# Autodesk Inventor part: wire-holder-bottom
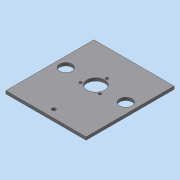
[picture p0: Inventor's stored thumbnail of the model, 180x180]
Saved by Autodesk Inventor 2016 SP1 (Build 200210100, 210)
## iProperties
Created: 2016-06
Part Number: wire-holder-bottom
Material: Generic
Document SubType Name: Modeling
Designer: Mohamed A.
Density: 1 g/cm^3
Appearance: Default
Author: Mohamed A.
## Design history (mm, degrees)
sketch "Sketch1"
  geometry: L1 (-41, 35)-(41, 35); L2 (41, 35)-(41, -35); L3 (41, -35)-(-41, -35); L4 (-41, -35)-(-41, 35); L5 (-41, 35)-(41, -35); L6 (41, 35)-(-41, -35); 1 further point
  constraints: 12 end point, 2 midpoint, 2 parallel, 1 horizontal, 1 perpendicular
  dimensions: "d0" = 82 distance of L2.end L3.end; "d1" = 70 distance of L1.end L2.end
extrude "Extrusion1" new body sketch "Sketch1" distance "d2" = 3; taper "d3" = 0 deg
sketch "Sketch2"
  geometry: C1 r 8.05 at (0, -4) reference; C2 r 2 at (9.922, -9.728) reference; C3 r 2 at (-9.922, -9.728) reference; C4 r 2 at (0, 7.457) reference; C5 r 1.4 at (-9.922, -9.728); C6 r 1.4 at (9.922, -9.728); C7 r 1.4 at (0, 7.457); C8 r 4.7 at (30.7, -4) reference; C9 r 4.7 at (-30.7, -4) reference; C10 r 6.3 at (30.7, -4); C11 r 6.3 at (-30.7, -4); C12 r 9.05 at (0, -4); 1 further point
  constraints: 6 centre point, 5 coincident
  dimensions: "d4" = 2.8 diameter of C5; "d5" = 2.8 diameter of C6; "d6" = 2.8 diameter of C7; "d9" = 12.6 diameter of C10; "d10" = 12.6 diameter of C11; "d19" = 1 radial gap between concentric circles of C1 C12
extrude "Extrusion2" cut sketch "Sketch2" distance "d7" = 3; taper "d8" = 0 deg
sketch "Sketch3"
  geometry: L1 (82, 0)-(0, 0) reference; L2 (82, 0)-(82, 3) reference; L3 (0, 3)-(82, 3) reference; L4 (0, 0)-(0, 3) reference; 1 further point
extrude "Extrusion3" join sketch "Sketch3" distance "d11" = 20; taper "d12" = 0 deg
sketch "Sketch4"
  geometry: L1 (0, -73)-(0, 53) reference; L2 (41, -55)-(-41, -55) reference; C1 r 2 at (0, -47); 1 further point
  constraints: 1 centre point, 1 point on line
  dimensions: "d13" = 4 diameter of C1; "d16" = 8 distance from line of C1.centre L2
extrude "Extrusion4" cut sketch "Sketch4" distance "d17" = 20; taper "d18" = 0 deg
body "Solid1"
node "Reference1"
node "Reference2"
node "Reference3"
node "Reference4"
node "Reference5"
node "Reference6"
node "Projected Loop1"
